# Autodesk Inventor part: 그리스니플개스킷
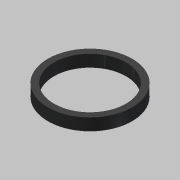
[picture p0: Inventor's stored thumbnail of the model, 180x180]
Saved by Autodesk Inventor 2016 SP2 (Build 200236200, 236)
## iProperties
Created: 2019-05
Part Number: 그리스니플개스킷
Material: 고무
Document SubType Name: Modeling
Designer: mduedu
Density: 1 g/cm^3
Appearance: 고무 - 검은색 - 버전 1.1
Author: mduedu
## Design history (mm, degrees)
sketch "스케치1"
  geometry: C1 r 3 at (0, 0); C2 r 3.5 at (0, 0); 1 further point
  constraints: 2 centre point, 2 coincident
  dimensions: "d0" = 6 diameter of C1; "d1" = 7 diameter of C2
extrude "돌출1" new body sketch "스케치1" distance "d2" = 1; taper "d3" = 0 deg
node "솔리드1"
